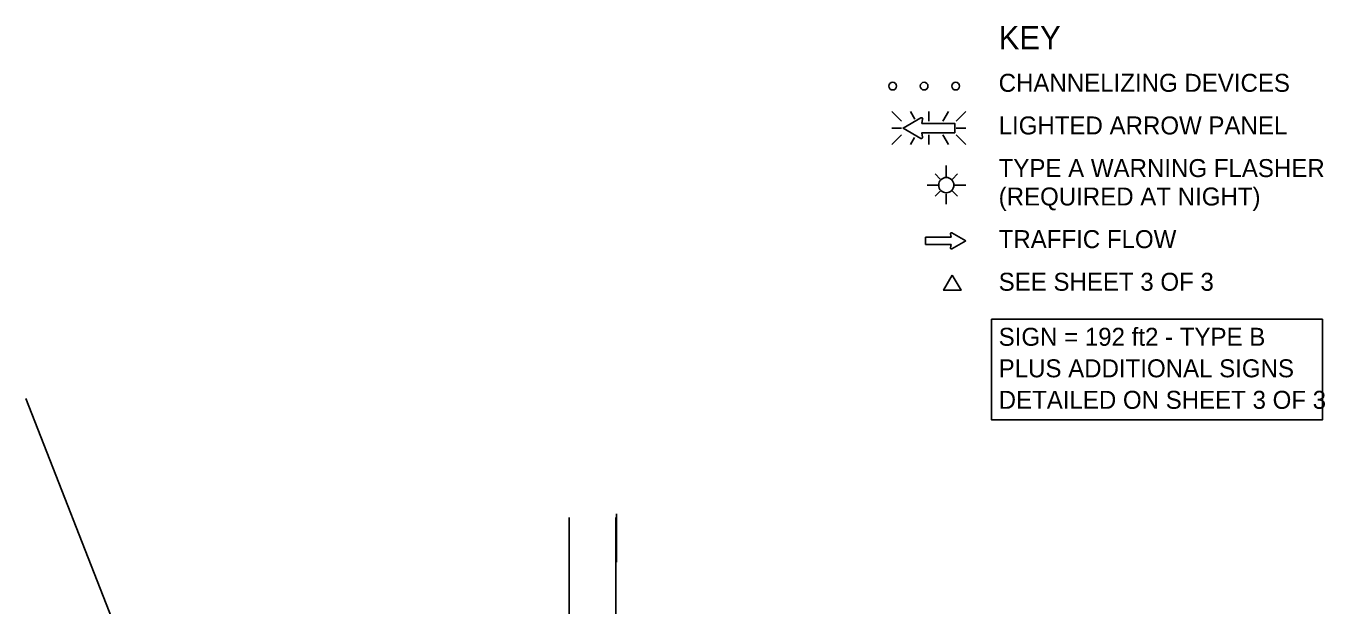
# Model space of a CAD drawing. Extents: x 16715 to 19504, y 7040 to 8495.
# Drawn here: x 16715 to 17386, y 8196 to 8495 of the extents above; entities that cross this region are included whole.
import ezdxf

# ---------------------------------------------------------------- set-up
doc = ezdxf.new("R2010")
doc.units = 0
for name, color, linetype in [('ALI_LEGAL_EX', 7, 'Continuous'), ('MT_SCRATCH_LEVEL_E', 7, 'Continuous'), ('TRAFFIC_SIGNS_PR', 7, 'Continuous'), ('TYPICAL_TEXT_DIMEN_EX', 7, 'Continuous'), ('TYPICAL_TEXT_DIMEN_PR', 7, 'Continuous')]:
    doc.layers.add(name, color=color, linetype=linetype)

msp = doc.modelspace()

# ---------------------------------------------------------------- linework, layer by layer
at = {"layer": 'ALI_LEGAL_EX'}
for p, q in [((16714.57, 8302.79), (16936.6, 7734.43)), ((16995.53, 8241.3), (16995.53, 7423.16)), ((17019.53, 8241.3), (17019.53, 7423.16))]:
    msp.add_line(p, q, dxfattribs=at)
msp.add_lwpolyline([(17019.95, 8218.16), (17019.95, 8243.16)], dxfattribs=at)
at = {"layer": 'MT_SCRATCH_LEVEL_E'}
for p, q in [((17192.9, 8386.23), (17179.64, 8386.23)), ((17179.64, 8386.23), (17179.64, 8382.48)), ((17192.58, 8388), (17192.9, 8386.23)), ((17200.51, 8384.37), (17193.27, 8388.49)), ((17193.27, 8380.23), (17200.51, 8384.37)), ((17179.64, 8382.48), (17192.9, 8382.48)), ((17192.9, 8382.48), (17192.58, 8380.71))]:
    msp.add_line(p, q, dxfattribs=at)
for centre, start, end in [((17193.04, 8388.08), 60.42484, 189.96381), ((17193.04, 8380.64), 170.03619, 299.77312)]:
    msp.add_arc(centre, 0.463, start, end, dxfattribs=at)
at = {"layer": 'TRAFFIC_SIGNS_PR'}
for p, q in [((17162.36, 8451.18), (17167.29, 8446.25)), ((17174.12, 8447.36), (17171.91, 8451.19)), ((17181.44, 8446.25), (17181.44, 8451.19)), ((17188.67, 8446.25), (17191.52, 8451.19)), ((17195.59, 8446.25), (17200.53, 8451.19)), ((17167.29, 8442.7), (17162.36, 8442.7)), ((17162.36, 8434.21), (17167.29, 8439.14)), ((17171.87, 8434.2), (17173.98, 8437.87)), ((17181.44, 8439.14), (17181.44, 8434.2)), ((17191.57, 8434.2), (17188.72, 8439.14)), ((17195.59, 8442.7), (17200.53, 8442.7)), ((17195.59, 8439.14), (17200.53, 8434.2)), ((17187.34, 8416.33), (17184.71, 8418.96)), ((17190.47, 8417.63), (17190.47, 8423.25)), ((17193.61, 8416.33), (17196.24, 8418.96)), ((17186.54, 8413.19), (17180.5, 8413.19)), ((17194.41, 8413.19), (17200.51, 8413.19)), ((17187.34, 8410.06), (17184.71, 8407.42)), ((17190.47, 8403.25), (17190.47, 8408.75)), ((17193.61, 8410.05), (17196.24, 8407.42))]:
    msp.add_line(p, q, dxfattribs=at)
for points in [[(17177.37, 8447.97), (17168.08, 8442.7), (17177.37, 8437.37)], [(17178.24, 8438), (17177.84, 8440.27), (17194.85, 8440.27), (17194.85, 8445.07), (17177.84, 8445.07), (17178.24, 8447.35)]]:
    msp.add_lwpolyline(points, dxfattribs=at)
for centre, radius in [((17162.7, 8464.38), 2), ((17179, 8464.38), 2), ((17195.3, 8464.38), 2), ((17190.47, 8413.19), 3.94)]:
    msp.add_circle(centre, radius, dxfattribs=at)
for centre, radius, start, end in [((17177.66, 8447.45), 0.598, 350.73078, 118.89165), ((17177.65, 8437.9), 0.597, 241.48329, 9.95933)]:
    msp.add_arc(centre, radius, start, end, dxfattribs=at)
at = {"layer": 'TYPICAL_TEXT_DIMEN_EX'}
msp.add_lwpolyline([(17213.89, 8343.77), (17384.99, 8343.77), (17384.99, 8291.76), (17213.89, 8291.76)], close=True, dxfattribs=at)
at = {"layer": 'TYPICAL_TEXT_DIMEN_PR'}
msp.add_lwpolyline([(17193.57, 8366.67), (17189.05, 8358.83), (17198.1, 8358.83)], close=True, dxfattribs=at)

# ---------------------------------------------------------------- texts
at = {"layer": 'TYPICAL_TEXT_DIMEN_EX'}
for s, height, p in [('KEY', 12, (17217.54, 8483.49)), ('CHANNELIZING DEVICES', 9.3, (17217.54, 8461.44)), ('LIGHTED ARROW PANEL', 9.3, (17217.54, 8439.39)), ('TYPE A WARNING FLASHER', 9.3, (17217.54, 8417.34)), ('(REQUIRED AT NIGHT)', 9.3, (17217.54, 8402.64)), ('TRAFFIC FLOW', 9.3, (17217.54, 8380.59)), ('SEE SHEET 3 OF 3', 9.3, (17217.54, 8358.54)), ('SIGN = 192 ft2 - TYPE B', 9.3, (17217.54, 8330.08)), ('PLUS ADDITIONAL SIGNS', 9.3, (17217.54, 8313.78)), ('DETAILED ON SHEET 3 OF 3', 9.3, (17217.54, 8297.48))]:
    msp.add_text(s, height=height, dxfattribs=at).set_placement(p)

doc.saveas('drawing.dxf')
